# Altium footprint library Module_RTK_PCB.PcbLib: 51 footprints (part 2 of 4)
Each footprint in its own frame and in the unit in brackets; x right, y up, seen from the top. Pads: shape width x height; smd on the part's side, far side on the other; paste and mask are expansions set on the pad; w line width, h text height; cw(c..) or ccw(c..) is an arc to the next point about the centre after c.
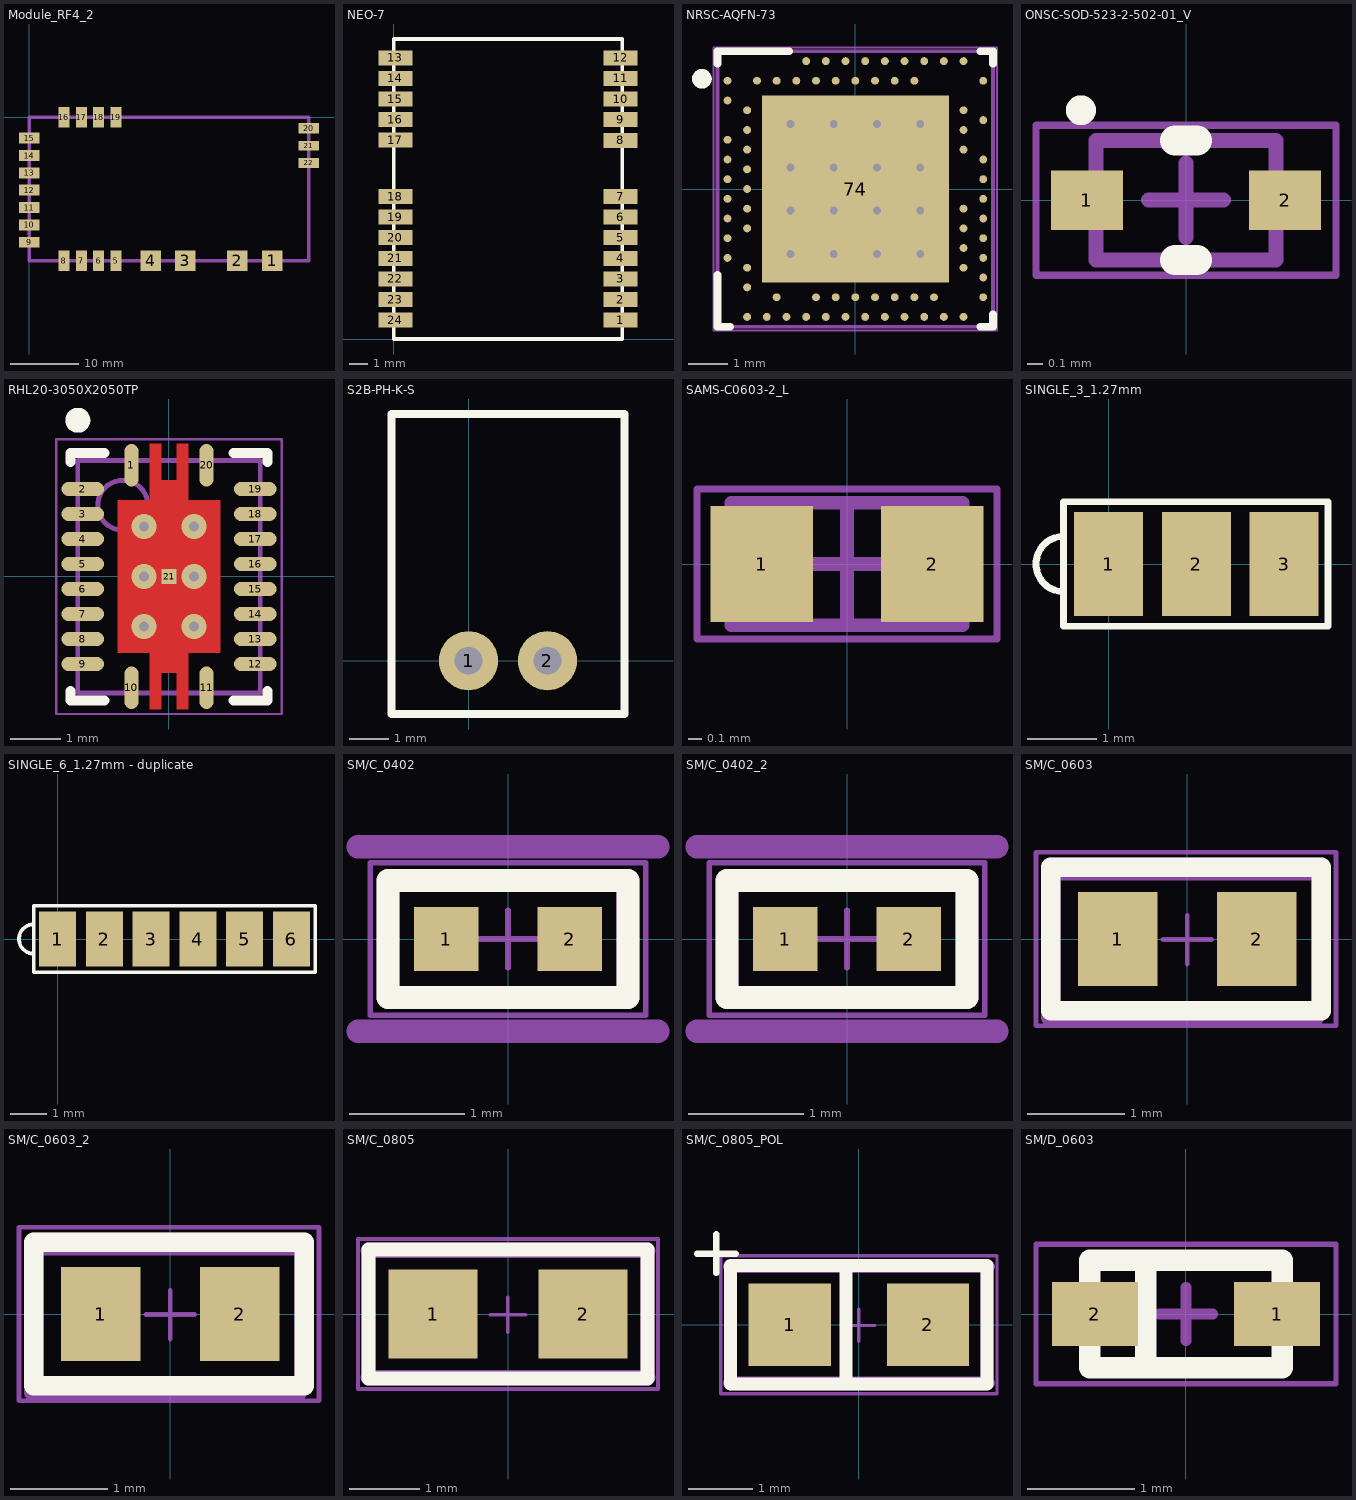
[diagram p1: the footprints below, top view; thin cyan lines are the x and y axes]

## Module_RF4_2 [mm]
pads (22):
  rect 3x3 smd: 1(35.56,-21) 2(30.48,-21) 3(22.86,-21) 4(17.78,-21)
  rect 1.6x3 smd: 5(12.7,-21) 6(10.16,-21) 7(7.62,-21) 8(5.08,-21) 16(5.08,0) 17(7.62,0) 18(10.16,0) 19(12.7,0)
  rect 3x1.6 smd: 9(0,-18.296) 10(0,-15.756) 11(0,-13.216) 12(0,-10.676) 13(0,-8.136) 14(0,-5.596) 15(0,-3.056) 20(40.925,-1.61)
  rect 3x1.4 smd: 21(40.925,-4.15) 22(40.925,-6.69)
Mechanical 1:
  lines w0.5: 0,-21 0,0 40.925,0 40.925,-21 0,-21
3D body: height 3, standoff 1, extent 2.492,-18.923 38.56,-2.032
3D body: height 1, standoff 0, extent 0.127,-20.955 40.925,0

## NEO-7 [mm] "GNSS module for GPS/QZSS, GLONASS"
pads (24):
  rect 1.8x0.8 smd: 1(12.1,1) 2(12.1,2.1) 3(12.1,3.2) 4(12.1,4.3) 5(12.1,5.4) 6(12.1,6.5) 7(12.1,7.6) 8(12.1,10.6) 9(12.1,11.7) 10(12.1,12.8) 11(12.1,13.9) 12(12.1,15) 13(0.1,15) 14(0.1,13.9) 15(0.1,12.8) 16(0.1,11.7) 17(0.1,10.6) 18(0.1,7.6) 19(0.1,6.5) 20(0.1,5.4) 21(0.1,4.3) 22(0.1,3.2) 23(0.1,2.1) 24(0.1,1)
Top Overlay:
  lines w0.2: 0,0 0,16 12.2,16 12.2,0 0,0

## NRSC-AQFN-73 [mm] "AQFN, 73-Leads, Body 7x7mm, Pitch 0.5mm"
height 0.85
pads (74):
  rect 4.75x4.75 smd: 74(0,0)
  round 0.2 smd: A8(-1.25,3.25) A10(-0.75,3.25) A12(-0.25,3.25) A14(0.25,3.25) A16(0.75,3.25) A18(1.25,3.25) A20(1.75,3.25) A22(2.25,3.25) A23(2.75,3.25) AA24(3.25,-2.25) AB2(-2.75,-2.5) AC5(-2,-2.75) AC9(-1,-2.75) AC11(-0.5,-2.75) AC13(0,-2.75) AC15(0.5,-2.75) AC17(1,-2.75) AC19(1.5,-2.75) AC21(2,-2.75) AC24(3.25,-2.75) AD2(-2.75,-3.25) AD4(-2.25,-3.25) AD6(-1.75,-3.25) AD8(-1.25,-3.25) AD10(-0.75,-3.25) AD12(-0.25,-3.25) AD14(0.25,-3.25) AD16(0.75,-3.25) AD18(1.25,-3.25) AD20(1.75,-3.25) AD22(2.25,-3.25) AD23(2.75,-3.25) B1(-3.25,2.75) B3(-2.5,2.75) B5(-2,2.75) B7(-1.5,2.75) B9(-1,2.75) B11(-0.5,2.75) B13(0,2.75) B15(0.5,2.75) B17(1,2.75) B19(1.5,2.75) B24(3.25,2.75) C1(-3.25,2.25) D2(-2.75,2) D23(2.75,2) E24(3.25,1.75) F2(-2.75,1.5) F23(2.75,1.5) G1(-3.25,1.25) H2(-2.75,1) H23(2.75,1) J1(-3.25,0.75) J24(3.25,0.75) K2(-2.75,0.5) L1(-3.25,0.25) L24(3.25,0.25) M2(-2.75,0) N1(-3.25,-0.25) N24(3.25,-0.25) P2(-2.75,-0.5) P23(2.75,-0.5) R1(-3.25,-0.75) R24(3.25,-0.75) T2(-2.75,-1) T23(2.75,-1) U1(-3.25,-1.25) U24(3.25,-1.25) V23(2.75,-1.5) W1(-3.25,-1.75) W24(3.25,-1.75) Y2(-2.75,-2) Y23(2.75,-2)
via -0.55,-0.55 diameter 0.5 hole 0.2
via 0.55,-0.55 diameter 0.5 hole 0.2
via -1.65,-0.55 diameter 0.5 hole 0.2
via -1.65,-1.65 diameter 0.5 hole 0.2
via 0.55,-1.65 diameter 0.5 hole 0.2
via -0.55,-1.65 diameter 0.5 hole 0.2
via -0.55,0.55 diameter 0.5 hole 0.2
via -1.65,0.55 diameter 0.5 hole 0.2
via 0.55,0.55 diameter 0.5 hole 0.2
via 1.65,0.55 diameter 0.5 hole 0.2
via 1.65,-1.65 diameter 0.5 hole 0.2
via 1.65,-0.55 diameter 0.5 hole 0.2
via -1.65,1.65 diameter 0.5 hole 0.2
via 0.55,1.65 diameter 0.5 hole 0.2
via -0.55,1.65 diameter 0.5 hole 0.2
via 1.65,1.65 diameter 0.5 hole 0.2
Top Overlay:
  circle w0.25: c-3.899,2.8 r0.125
  lines w0.2: -3.5,-2.183 -3.5,-3.5 -3.183,-3.5 ; -3.5,3.183 -3.5,3.5 -1.683,3.5 ; 3.183,-3.5 3.5,-3.5 3.5,-3.183 ; 3.183,3.5 3.5,3.5 3.5,3.183
Mechanical 13:
  lines w0.1: -3.5,-3.5 -3.5,3.5 3.5,3.5 3.5,-3.5 -3.5,-3.5
Mechanical 15:
  lines w0.05: -3.6,-3.6 3.6,-3.6 3.6,3.6 -3.6,3.6 -3.6,-3.6
  lines w0.1: -0.5,0 0.5,0 ; 0,-0.5 0,0.5
3D body: height 0.85, standoff 0.02, extent -3.5,-3.5 3.5,3.5

## ONSC-SOD-523-2-502-01_V [mm] "SOD, 2-Leads, Body 1.2x0.8mm"
height 0.7
pads (2):
  rect 0.48x0.4 smd: 1(-0.66,0) 2(0.66,0)
Top Overlay:
  circle w0.1: c-0.7,0.6 r0.05
  lines w0.2: -0.074,-0.4 0.074,-0.4 ; -0.074,0.4 0.074,0.4
Mechanical 13:
  lines w0.1: -0.6,-0.4 0.6,-0.4 0.6,0.4 -0.6,0.4 -0.6,-0.4
Mechanical 15:
  lines w0.05: -1,-0.5 -1,0.5 1,0.5 1,-0.5 -1,-0.5
  lines w0.1: -0.25,0 0.25,0 ; 0,-0.25 0,0.25
3D body: height 0.7, standoff 0, extent -0.6,-0.4 0.6,0.4

## RHL20-3050X2050TP [mm] "QFN, 20-Leads, Body 4.5x3.5mm, Pitch 0.5mm, Thermal Pad 3.05x2.05mm, TI Recommended"
height 1
pads (21):
  oval 0.28x0.85 smd paste-0.025 mask+0.07: 1(-0.75,2.225) 10(-0.75,-2.225) 11(0.75,-2.225) 20(0.75,2.225)
  oval 0.85x0.28 smd paste-0.025 mask+0.07: 2(-1.725,1.75) 3(-1.725,1.25) 4(-1.725,0.75) 5(-1.725,0.25) 6(-1.725,-0.25) 7(-1.725,-0.75) 8(-1.725,-1.25) 9(-1.725,-1.75) 12(1.725,-1.75) 13(1.725,-1.25) 14(1.725,-0.75) 15(1.725,-0.25) 16(1.725,0.25) 17(1.725,0.75) 18(1.725,1.25) 19(1.725,1.75)
  rect 0.3x0.3 smd paste-0.15 mask+0: 21(0,0)
via 0.5,-1 diameter 0.5 hole 0.2
via 0.5,0 diameter 0.5 hole 0.2
via 0.5,1 diameter 0.5 hole 0.2
via -0.5,-1 diameter 0.5 hole 0.2
via -0.5,0 diameter 0.5 hole 0.2
via -0.5,1 diameter 0.5 hole 0.2
Top Layer:
  region: 0.16,2.65 0.16,1.925 -0.16,1.925 -0.16,2.65 -0.39,2.65 -0.39,1.525 -1.025,1.525 -1.025,-1.525 -0.39,-1.525 -0.39,-2.65 -0.16,-2.65 -0.16,-1.925 0.16,-1.925 0.16,-2.65 0.39,-2.65 0.39,-1.525 1.025,-1.525 1.025,1.525 0.39,1.525 0.39,2.65
Top Overlay:
  circle w0.25: c-1.825,3.125 r0.125
  lines w0.2: -1.975,-2.29 -1.975,-2.475 -1.29,-2.475 ; -1.975,2.29 -1.975,2.475 -1.29,2.475 ; 1.29,-2.475 1.975,-2.475 1.975,-2.29 ; 1.29,2.475 1.975,2.475 1.975,2.29
Top Paste:
  region: 0.15,1.47 0.15,0.15 0.97,0.15 0.97,1.47
  region: 0.97,-1.47 0.97,-0.15 0.15,-0.15 0.15,-1.47
  region: -0.15,-1.47 -0.15,-0.15 -0.97,-0.15 -0.97,-1.47
  region: -0.97,1.47 -0.97,0.15 -0.15,0.15 -0.15,1.47
  region: 0.39,-2.625 0.39,-1.725 0.16,-1.725 0.16,-2.625
  region: 0.16,2.625 0.16,1.725 0.39,1.725 0.39,2.625
  region: -0.16,-2.625 -0.16,-1.725 -0.39,-1.725 -0.39,-2.625
  region: -0.39,2.625 -0.39,1.725 -0.16,1.725 -0.16,2.625
Mechanical 13:
  circle w0.1: c-0.925,1.425 r0.5
  lines w0.1: -1.825,-2.325 -1.825,2.325 1.825,2.325 1.825,-2.325 -1.825,-2.325
Mechanical 15:
  lines w0.05: -2.25,-2.75 -2.25,2.75 2.25,2.75 2.25,-2.75 -2.25,-2.75
  lines w0.1: -0.5,0 0.5,0 ; 0,-0.5 0,0.5
3D body: height 1, standoff 0, extent -1.825,-2.325 1.825,2.325

## S2B-PH-K-S [mm]
height 4.8
pads (2):
  round 1.5 hole 0.7: 1(0,0) 2(2,0)
Top Overlay:
  lines w0.2: -1.95,-1.35 3.95,-1.35 3.95,6.25 -1.95,6.25 -1.95,-1.35

## SAMS-C0603-2_L [mm] "Chip Capacitor, 2-Leads, Body 1.70x0.90mm, IPC High Density"
height 0.9
pads (2):
  rect 0.75x0.85 smd: 1(-0.625,0) 2(0.625,0)
Mechanical 13:
  lines w0.1: -0.85,-0.45 0.85,-0.45 0.85,0.45 -0.85,0.45 -0.85,-0.45
Mechanical 15:
  lines w0.05: -1.1,-0.55 1.1,-0.55 1.1,0.55 -1.1,0.55 -1.1,-0.55
  lines w0.1: -0.45,0 0.45,0 ; 0,-0.45 0,0.45
3D body: height 0.9, standoff 0, extent 0.55,-0.45 0.85,0.45
3D body: height 0.9, standoff 0, extent -0.85,-0.45 -0.55,0.45
3D body: height 0.9, standoff 0, extent -0.55,-0.45 0.55,0.45

## SINGLE_3_1.27mm [mm] "Connector; Header; 3 Position"
height 4.8
pads (3):
  rect 1x1.5 smd: 1(0,0) 2(1.27,0) 3(2.54,0)
Top Overlay:
  lines w0.1: -0.65,-0.4 cw(c-0.65,0) -0.65,0.4 ; -0.65,-0.9 3.175,-0.9 3.175,0.9 -0.65,0.9 -0.65,-0.9

## SINGLE_6_1.27mm - duplicate [mm] "Connector; Header; 6 Position"
height 4.8
pads (6):
  rect 1x1.5 smd: 1(0,0) 2(1.27,0) 3(2.54,0) 4(3.81,0) 5(5.08,0) 6(6.35,0)
Top Overlay:
  lines w0.1: -0.65,-0.4 cw(c-0.65,0) -0.65,0.4 ; -0.65,-0.9 7,-0.9 7,0.9 -0.65,0.9 -0.65,-0.9

## SM/C_0402 [mil]
pads (2):
  rect 22x22 smd: 1(-21,0) 2(21,0)
Top Overlay:
  lines w7.87: -41,-20 -41,20 41,20 41,-20 -41,-20
Mechanical 11:
  lines w7.87: -51.18,-31.48 51.18,-31.48 ; -51.18,31.48 51.18,31.48
  text ".designator" at -43.31,-19.68 h39.37
Mechanical 13:
  lines w7.87: -41,-20 41,-20 41,20 -41,20 -41,-20
Mechanical 15:
  lines w1.97: 0,0 0,9.84 0,0 ; 0,0 -9.84,0 0,0 ; 0,0 9.85,0 0,0 ; 0,0 0,-9.85 0,0 ; -47,-26 -47,26 47,26 47,-26 -47,-26
3D body "User Library-cap_0402.step": height 19.68, standoff 0, extent -19.68,-9.84 19.69,9.84

## SM/C_0402_2 [mil]
pads (2):
  rect 22x22 smd: 1(-21,0) 2(21,0)
Top Overlay:
  lines w7.87: -41,-20 41,-20 41,20 -41,20 -41,-20
Mechanical 11:
  lines w7.87: -51.18,-31.48 51.18,-31.48 ; -51.18,31.48 51.18,31.48
  text ".designator" at -43.31,-19.68 h39.37
Mechanical 13:
  lines w7.87: -41,-20 -41,20 41,20 41,-20 -41,-20
Mechanical 15:
  lines w1.97: 0,0 0,9.84 0,0 ; 0,0 -9.84,0 0,0 ; 0,0 9.85,0 0,0 ; 0,0 0,-9.85 0,0 ; -47,-26 47,-26 47,26 -47,26 -47,-26
3D body "User Library-cap_0402.step": height 19.68, standoff 0, extent -19.68,-9.84 19.7,9.85

## SM/C_0603 [mil]
height 188.98
pads (2):
  rect 32x38 smd: 1(-28,0) 2(28,0)
Top Overlay:
  lines w7.87: -55,-29 54,-29 54,29 -55,29 -55,-29
Mechanical 11:
  lines w7.87: -55.12,-31.5 51.18,-31.5 ; -55.12,27.56 51.18,27.56
  text ".designator" at -55.12,-19.68 h39.37
Mechanical 13:
  lines w7.87: -55,-29 -55,29 54,29 54,-29 -55,-29
Mechanical 15:
  lines w1.97: -0.01,-0.26 -0.01,9.58 -0.01,-0.26 ; -0.01,-0.26 -9.85,-0.26 -0.01,-0.26 ; -0.01,-0.26 9.84,-0.26 -0.01,-0.26 ; -0.01,-0.26 -0.01,-10.1 -0.01,-0.26 ; -61,-35 -61,35 60,35 60,-35 -61,-35
3D body "User Library-cap_0603-1.STEP": height 31.5, standoff 0, extent -31.5,-16 31.49,15.49

## SM/C_0603_2 [mil]
pads (2):
  rect 32x38 smd: 1(-28,0) 2(28,0)
Top Overlay:
  lines w7.87: -55,-29 54,-29 54,29 -55,29 -55,-29
Mechanical 11:
  lines w7.87: -55.12,-31.5 51.18,-31.5 ; -55.12,27.56 51.18,27.56
  text ".designator" at -55.12,-19.68 h39.37
Mechanical 13:
  lines w7.87: -55,-29 -55,29 54,29 54,-29 -55,-29
Mechanical 15:
  lines w1.97: -0.01,-0.26 -0.01,9.58 -0.01,-0.26 ; -0.01,-0.26 -9.85,-0.26 -0.01,-0.26 ; -0.01,-0.26 9.84,-0.26 -0.01,-0.26 ; -0.01,-0.26 -0.01,-10.1 -0.01,-0.26 ; -61,-35 -61,35 60,35 60,-35 -61,-35
3D body "User Library-cap_0603-1.STEP": height 31.5, standoff 0, extent -31.5,-16 31.49,15.49

## SM/C_0805 [mil]
pads (2):
  rect 50x50 smd: 1(-42,0) 2(42,0)
Top Overlay:
  lines w7.87: -78,-36 -78,36 78,36 78,-36 -78,-36
Mechanical 11:
  lines w7.87: -78.74,-35.43 78.74,-35.43 ; -78.74,35.43 78.74,35.43
  text ".designator" at -70.87,-19.68 h39.37
Mechanical 13:
  lines w7.87: -78,-36 78,-36 78,36 -78,36 -78,-36
Mechanical 15:
  lines w1.97: -0.01,-0.38 -0.01,9.46 -0.01,-0.38 ; -0.01,-0.38 -9.85,-0.38 -0.01,-0.38 ; -0.01,-0.38 9.84,-0.38 -0.01,-0.38 ; -0.01,-0.38 -0.01,-10.23 -0.01,-0.38 ; -84,-42 -84,42 84,42 84,-42 -84,-42
3D body "User Library-cap_0805-1.step": height 47.24, standoff 0, extent -39.37,-24 39.37,23.24

## SM/C_0805_POL [mil]
pads (2):
  rect 50x50 smd: 1(-42,0) 2(42,0)
Top Overlay:
  lines w3.94: -98.43,43.31 -74.8,43.31 ; -86.61,31.5 -86.61,55.12
  lines w7.87: -7.87,-36 -7.87,36 ; -78,-36 -78,36 78,36 78,-36 -78,-36
Mechanical 11:
  lines w7.87: -78.74,-35.43 78.74,-35.43 ; -78.74,35.43 78.74,35.43
Mechanical 13:
  lines w7.87: -78,-36 78,-36 78,36 -78,36 -78,-36
Mechanical 15:
  lines w1.97: -0.01,-0.38 -0.01,9.46 -0.01,-0.38 ; -0.01,-0.38 -9.85,-0.38 -0.01,-0.38 ; -0.01,-0.38 9.84,-0.38 -0.01,-0.38 ; -0.01,-0.38 -0.01,-10.23 -0.01,-0.38 ; -84,-42 -84,42 84,42 84,-42 -84,-42
3D body "User Library-cap_0805-1.step": height 47.24, standoff 0, extent -39.37,-24 39.37,23.24

## SM/D_0603 [mm] "Diode Package 0603"
height 0.85
pads (2):
  rect 0.8x0.6 smd: 1(0.85,0) 2(-0.85,0)
Top Overlay:
  lines w0.2: -0.4,-0.5 -0.375,-0.5 -0.375,0.5 ; -0.9,-0.5 -0.9,0.5 0.9,0.5 0.9,-0.5 -0.9,-0.5
Mechanical 11:
  text ".designator" at 0,1 h1
  text ".Comment" at 0,-1 h1
Mechanical 15:
  lines w0.05: -1.4,-0.65 -1.4,0.65 1.4,0.65 1.4,-0.65 -1.4,-0.65
  lines w0.1: -0.25,0 0.25,0 ; 0,-0.25 0,0.25
3D body: height 0.85, standoff 0.75, extent -0.9,-0.5 -0.4,0.5
3D body: height 0.85, standoff 0.75, extent -0.4,-0.5 0.9,0.5
3D body: height 0.75, standoff 0, extent -0.9,-0.5 0.9,0.5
